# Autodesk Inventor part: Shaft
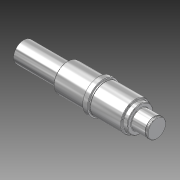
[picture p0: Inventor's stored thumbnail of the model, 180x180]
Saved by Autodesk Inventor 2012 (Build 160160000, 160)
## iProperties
Created: 2007-07
Part Number: Shaft
Material: Steel
Document SubType Name: Modeling
Designer: Designer
Density: 1 g/cm^3
CustomPartVersion: 1
Author: Designer
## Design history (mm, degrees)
sketch "Main Sketch"
  geometry: L1 (0, 0)-(219.8, 0) reference; L2 (0, 0)-(0, 11); L3 (0, 11)-(48, 11); L4 (48, 11)-(48, 15); L5 (48, 15)-(157, 15); L6 (157, 15)-(157, 17.5); L7 (162, 17.5)-(162, 16); L8 (157, 17.5)-(162, 17.5); L9 (197, 16)-(197, 14); L10 (162, 16)-(197, 16); L11 (202, 14)-(202, 10); L12 (197, 14)-(202, 14); L13 (219.8, 10)-(219.8, 0); L14 (202, 10)-(219.8, 10)
  constraints: 28 end point, 7 vertical, 2 horizontal
  dimensions: "d3" = 22 diameter of L3 L1 (derived); "d4" = 30 diameter of L5 L1 (derived); "d5" = 35 diameter of L8 L1 (derived); "d6" = 32 diameter of L10 L1 (derived); "d7" = 28 diameter of L12 L1 (derived); "d8" = 20 diameter of L14 L1 (derived)
revolve "Revolution1" sketch "Main Sketch" stored, may be unused: angle "d9" = 0 deg
chamfer "Chamfer24" distance "d83" = 0.5; stored, may be unused: second distance "d84" = 0.125, angle "d85" = 45 deg
node "Relief3"
chamfer "Chamfer20" distance "d69" = 0.5; stored, may be unused: second distance "d70" = 0.125, angle "d71" = 45 deg
chamfer "Chamfer18" distance "d63" = 0.5; stored, may be unused: second distance "d64" = 0.125, angle "d65" = 45 deg
chamfer "Chamfer14" distance "d51" = 0.5; stored, may be unused: second distance "d52" = 0.125, angle "d53" = 45 deg
chamfer "Chamfer13" distance "d48" = 0.5; stored, may be unused: second distance "d49" = 0.125, angle "d50" = 45 deg
chamfer "Chamfer11" distance "d42" = 0.5; stored, may be unused: second distance "d43" = 0.125, angle "d44" = 45 deg
chamfer "Chamfer12" distance "d45" = 0.5; stored, may be unused: second distance "d46" = 0.125, angle "d47" = 45 deg
fillet "Fillet1" dims "d13" = 2
feature "iFeature2:1"
feature "iFeature27:1"
body "Solid1"
feature "iFeature2:4"
other parameters: "d0" = 0, "d1" = 0, "d2" = 0
